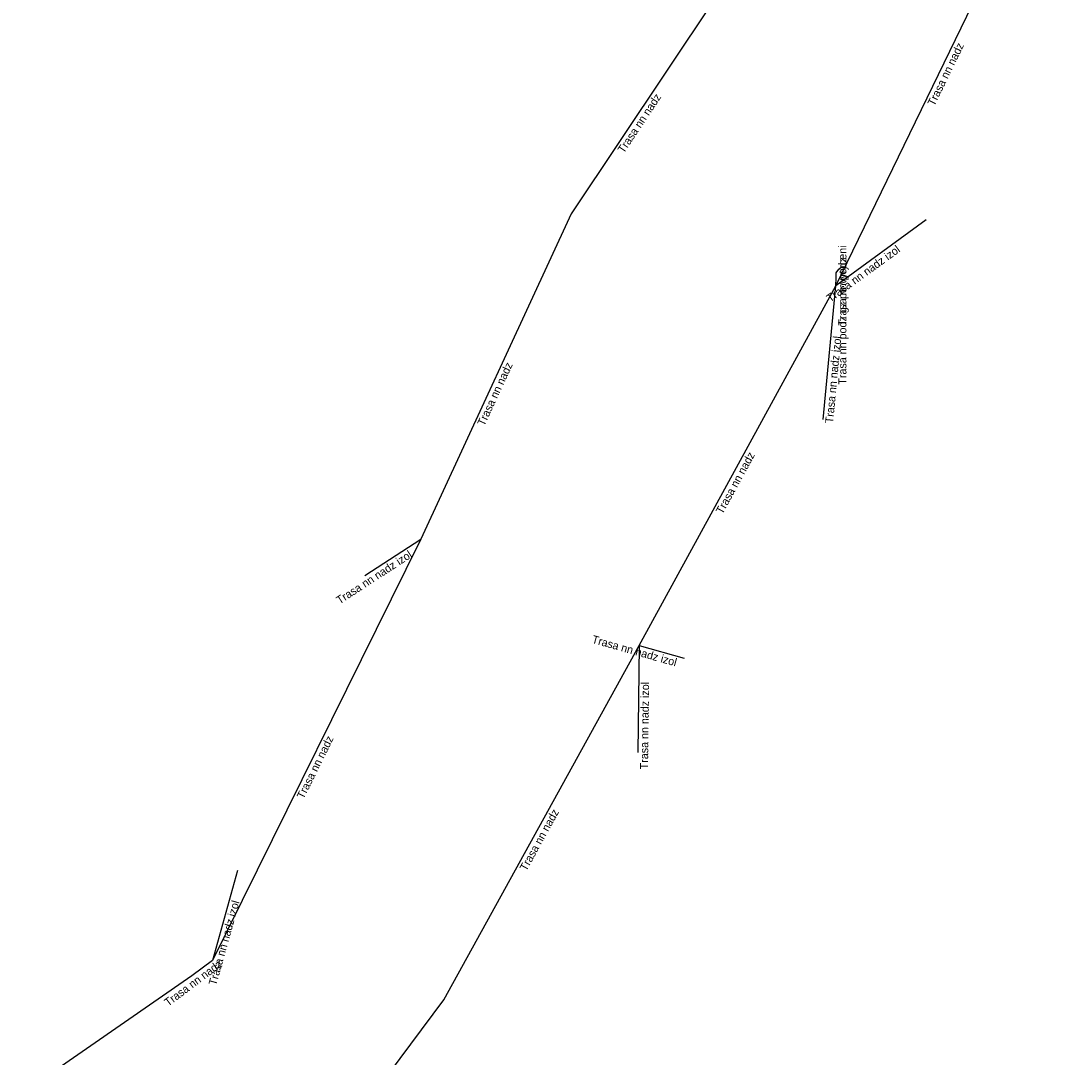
# Model space of a CAD drawing. Extents: x -772942 to -772530, y -1033745 to -1033298.
# Drawn here: x -772879.6 to -772814.8, y -1033558.1 to -1033493.3 of the extents above; entities that cross this region are included whole.
import ezdxf

# ---------------------------------------------------------------- set-up
doc = ezdxf.new("R2010")
doc.units = 0
doc.layers.add('Popiskový text - Ostatní atributy Trasy', color=7, linetype='Continuous')
doc.layers.add('Spojnice NN', color=7, linetype='Continuous')

msp = doc.modelspace()

# ---------------------------------------------------------------- linework, layer by layer
at = {"layer": 'Spojnice NN'}
for points in [[(-772828.67, -1033509.88), (-772814.771, -1033481.263)], [(-772836.223, -1033491.921), (-772845.188, -1033505.391)], [(-772845.188, -1033505.391), (-772854.587, -1033525.713)], [(-772823.02, -1033505.763), (-772828.67, -1033509.88)], [(-772828.67, -1033509.88), (-772828.65, -1033509.39), (-772828.65, -1033509.08), (-772828.48, -1033508.84), (-772828.31, -1033508.7)], [(-772828.67, -1033509.88), (-772828.65, -1033509.39), (-772828.65, -1033509.08), (-772828.48, -1033508.84), (-772828.31, -1033508.7)], [(-772840.942, -1033532.355), (-772828.67, -1033509.88)], [(-772829.462, -1033518.23), (-772828.67, -1033509.88)], [(-772854.587, -1033525.713), (-772867.59, -1033552.047)], [(-772858.075, -1033527.992), (-772854.587, -1033525.713)], [(-772853.143, -1033554.495), (-772840.942, -1033532.355)], [(-772840.942, -1033532.355), (-772841.03, -1033539.047)], [(-772840.942, -1033532.355), (-772838.122, -1033533.15)], [(-772866.02, -1033546.422), (-772867.59, -1033552.047)], [(-772867.59, -1033552.047), (-772868.869, -1033553.006)], [(-772868.869, -1033553.006), (-772888.63, -1033566.69)], [(-772864.11, -1033569.24), (-772853.143, -1033554.495)]]:
    msp.add_lwpolyline(points, dxfattribs=at)

# ---------------------------------------------------------------- texts
at = {"layer": 'Popiskový text - Ostatní atributy Trasy'}
for s, rotation, p in [('Trasa nn nadz', 64.0946, (-772822.511, -1033498.687)), ('Trasa nn nadz', 56.35413, (-772841.909, -1033501.637)), ('Trasa nn nadz izol', 36.081, (-772829.011, -1033510.932)), ('Trasa nn podz gz po vytyceni', 90, (-772828, -1033516.056)), ('Trasa nn podz', 90, (-772828, -1033512.371)), ('Trasa nn nadz izol', 84.57829, (-772828.834, -1033518.487)), ('Trasa nn nadz', 65.17928, (-772850.618, -1033518.682)), ('Trasa nn nadz', 61.36418, (-772835.744, -1033524.191)), ('Trasa nn nadz izol', 33.15892, (-772859.65, -1033529.797)), ('Trasa nn nadz izol', 344.26548, (-772843.933, -1033532.187)), ('Trasa nn nadz izol', 89.25088, (-772840.393, -1033540.099)), ('Trasa nn nadz', 63.72112, (-772861.899, -1033541.99)), ('Trasa nn nadz', 61.14154, (-772847.992, -1033546.495)), ('Trasa nn nadz izol', 74.40131, (-772867.36, -1033553.637)), ('Trasa nn nadz', 36.86273, (-772870.358, -1033554.935))]:
    msp.add_text(s, height=0.5, rotation=rotation, dxfattribs=at).set_placement(p)

doc.saveas('drawing.dxf')
